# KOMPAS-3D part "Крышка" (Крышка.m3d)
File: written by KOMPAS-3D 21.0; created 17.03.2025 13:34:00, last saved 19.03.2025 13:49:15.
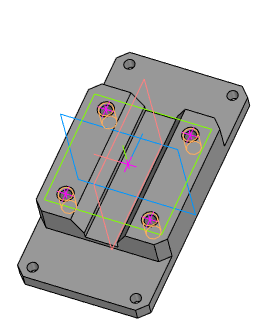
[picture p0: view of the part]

Document properties: Автор: fedorov478@gmail.com; Полное имя файла: C:\Users\User\Desktop\Ринат все\Ринат\Перспектива\Крышка.m3d

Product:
- Part/product: Крышка
    Масса: 0.51788
  - Body: Тело 4
      Масса: 0.457319

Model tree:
1. Эскиз:3
2. Элемент выдавливания:4
     Расстояние 1 = 106
3. Эскиз:5
4. Элемент выдавливания:9
     Расстояние 1 = 60
5. Эскиз:6  (with: Элемент выдавливания:4)
6. Элемент выдавливания:10
     Расстояние 2 = 10
7. Фаска:1  (with: Элемент выдавливания:9, Элемент выдавливания:4)
     Угол = 45; Длина 1 = 4; Длина 2 = 4
8. Эскиз:7  (with: Элемент выдавливания:9)
9. Отверстие:5  (with: Элемент выдавливания:9)  (labels: M6)
     Глубина выреза = 12; Диаметр отверстия = 4.91747; Угол конуса дна = 118; Расстояние 1 = 10; Расстояние 2 = 10
10. M6  (with: Элемент выдавливания:9)  (labels: M6; cil0_24705-2004 coarse)
     Длина резьбы = 10; Шаг резьбы = 1; Номинальный диаметр резьбы = 6
11. Фаска:2  (with: Отверстие:5)
     Угол = 45; Длина 1 = 1; Длина 2 = 1
12. Массив по точкам:2
13. Экземпляр ( 3 )  (with: Отверстие:5, Эскиз:7)  (labels: 0x0,5)
14. Фаска:2
15. Экземпляр ( 1 )  (with: Отверстие:5, Эскиз:7)  (labels: 0x0,5)
16. Фаска:2
17. Экземпляр ( 2 )  (with: Отверстие:5, Эскиз:7)  (labels: 0x0,5)
18. Фаска:2

Expressions: v868/2; 15.0+19-18.89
